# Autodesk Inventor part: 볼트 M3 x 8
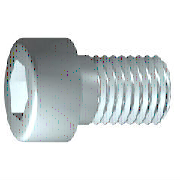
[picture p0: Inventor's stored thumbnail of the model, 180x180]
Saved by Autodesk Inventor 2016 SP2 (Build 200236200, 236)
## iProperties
IsCustomPart: 0
Created: 2012-02
Part Number: 볼트 M3 x 8
Material: 스테인리스강
Description: 6각 소켓 머리 캡 나사
Document SubType Name: Modeling
Standard: ISO 4762
Designer: mduedu
Standard Revision: Fourth edition 2004-03-01
Standards Organization: ISO
Language: ko-KR
Size Designation: M3 x 8
Categories: <MemberInstance><Categories><Category DisplayName="조임쇠" InternalName="e4da775c-781d-43d5-af7c-5136215cf5a6" Mnemonic="FSTN"><Category DisplayName="볼트" InternalN
Density: 8.08 g/cm^3
Mass: 0.955869 g
Surface Area: 1.83001 cm^2
Volume: 0.118301 cm^3
Appearance: 반광택
Author: mduedu
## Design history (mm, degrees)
sketch "스케치1"
  geometry: L1 (-0.867, 0)-(8, 0); L2 (8, 0)-(8, 1.5); L3 (8, 1.5)-(1.25, 1.5); L4 (1.25, 1.5)-(0.943, 1.5); L5 (0.943, 1.5)-(0, 1.5); L6 (0, 1.5)-(0, 2.75); L7 (0, 2.75)-(-3, 2.75); L8 (-3, 2.75)-(-3, 1.443); L9 (-3, 1.443)-(-1.7, 1.443); L10 (-1.7, 1.443)-(-0.867, 0); L11 (-5.2, 0)-(10.2, 0) reference; L12 (0, -0.55)-(0, 3.3) reference; L13 (1.25, 1.5)-(0, 1.5)
  constraints: 22 end point, 6 parallel, 2 collinear, 2 perpendicular, 1 horizontal, 1 point on line
  dimensions: "d1" = 6.75 distance from line of L3.end L2 (= GEL); "d2" = 0.30683 distance of L4.end L3.end (computed from GAL); "d3" = 3 distance between parallel lines of L8 L6 (= KOH); "d4" = 1.3 distance of L8.end L9.end (= INTI); "d5" = 60 deg angle of L10 L1; "d6" = 3 diameter of L3 L1 (= GD); "d7" = 3 diameter of L5 L1 (= BDM); "d8" = 2.88675 diameter of L9 L1 (= 1.1547 x SW); "d9" = 5.5 diameter of L7 L1 (= KOD); "d26" = 8 distance between parallel lines of L12 L2 (= NLG)
revolve "본체" sketch "스케치1" stored, may be unused: angle "d10" = 90 deg
sketch "스케치2"
  geometry: L1 (0, -3.85)-(0, 3.85) reference; L2 (-3.85, 0)-(3.85, 0) reference; L3 (1.443, 0)-(0.722, -1.25); L4 (0.722, -1.25)-(-0.722, -1.25); L5 (-0.722, -1.25)-(-1.443, 0); L6 (-1.443, 0)-(-0.722, 1.25); L7 (-0.722, 1.25)-(0.722, 1.25); L8 (0.722, 1.25)-(1.443, 0); 2 further points
  constraints: 12 end point, 1 coincident, 1 horizontal alignment, 1 point on line, 12 other
extrude "슬롯" join sketch "스케치2" stored distance "d11" = 10; taper "d12" = 0 deg
workplane "Work Plane1"
fillet "Fillet2" dims "d30" = 0.1 (= R)
body "Solid1"
fillet "모깎기1" dims "d17" = 0.3 (= RR)
feature "스레드" dims "d13" = 6.75 (= GEL), "d14" = 0
chamfer "모따기1" distance "d15" = 0.30673 (= -0.5 x SPD + 0.5 x GD); stored, may be unused: second distance "d16" = 0.30673 (= GUL), angle "d27" = 45 deg
other parameters: "GD" = 3 [user parameter; used in 2 equation terms], "NLG" = 8 [user parameter; used in 1 equation term], "GEL" = 6.75 [user parameter; used in 2 equation terms], "KOD" = 5.5 [user parameter; used in 1 equation term], "KOH" = 3 [user parameter; used in 1 equation term], "INTI" = 1.3 [user parameter; used in 1 equation term], "GAL" = 0.30673 (= 0.61345 x PTC) [user parameter; used in 1 equation term], "GUL" = 0.30673 (= 0.61345 x PTC) [user parameter; used in 1 equation term], "BDM" = 3 (= NND) [user parameter; used in 1 equation term], "SW" = 2.5 [user parameter; used in 2 equation terms], "RR" = 0.3 [user parameter; used in 1 equation term], "SPD" = 2.38655 (= NND - 1.2269 x PTC) [user parameter; used in 1 equation term], "d19" = 0, "d28" = 0, "d29" = 0, "R" = 0.1 [user parameter; used in 1 equation term], "TOA" = 30 deg [user parameter], "GD1" = 2.38655 (= THREADDIA - 1.2269 x PTC) [user parameter], "THREADDIA" = 3 [user parameter; used in 1 equation term], "FAWI" = 45 deg [user parameter], "PTC" = 0.5 [user parameter; used in 5 equation terms], "NND" = 3 [user parameter; used in 2 equation terms], "E0" = 2.8875 (= 1.155 x SW) [user parameter]
